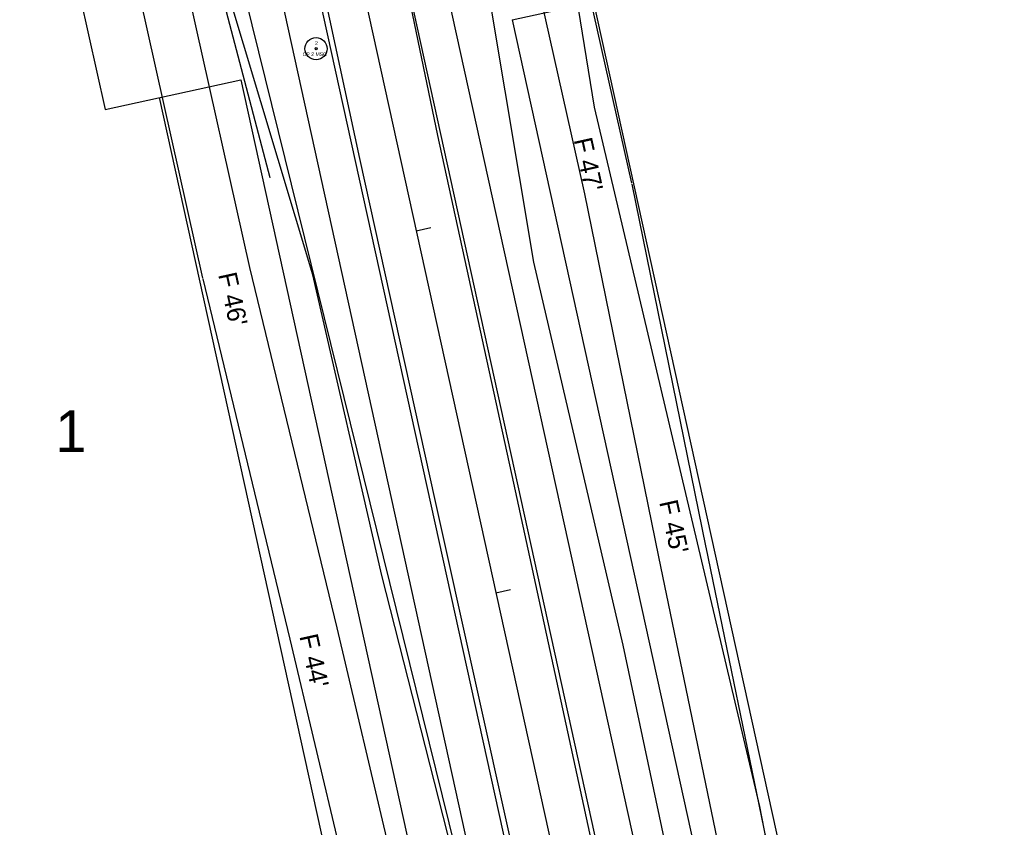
# Model space of a CAD drawing. Extents: x 2519952 to 2531965, y 848341 to 887632.
# Drawn here: x 2521510 to 2521778.9, y 868929.6 to 869147.3 of the extents above; entities that cross this region are included whole.
import ezdxf

# ---------------------------------------------------------------- set-up
doc = ezdxf.new("R2010")
doc.units = 0
for name, color, linetype in [('RD_EV_JW', 7, 'Continuous'), ('RD_EX_DV_Prop', 7, 'Continuous'), ('RD_EX_DV_TX_Prop', 7, 'Continuous'), ('RD_EX_H2O', 7, 'Continuous'), ('RD_EX_Road', 7, 'Continuous'), ('RD_EX_RW', 7, 'Continuous'), ('RD_EX_VEG', 7, 'Continuous'), ('RD_HC_Cl', 7, 'Continuous'), ('RD_HC_Data', 7, 'Continuous'), ('RD_HC_Data_Tic', 7, 'Continuous'), ('RD_HC_txCode', 7, 'Continuous'), ('RD_PD_CstnLmt', 7, 'Continuous'), ('RD_PD_DR_ErosCtrl', 7, 'Continuous'), ('RD_PD_Final_TrvlWay', 7, 'Continuous'), ('RD_PD_GR', 7, 'Continuous'), ('RD_PD_RW', 7, 'Continuous'), ('RD_PD_TX_CstnLmt', 7, 'Continuous'), ('RD_SMD_Locator', 7, 'Continuous')]:
    doc.layers.add(name, color=color, linetype=linetype)

msp = doc.modelspace()

# ---------------------------------------------------------------- linework, layer by layer
at = {"layer": 'RD_EV_JW'}
for points in [[(2521729.69, 868713.74), (2521695.24, 868873.24), (2521672.84, 868978.69), (2521648.76, 869082.03), (2521633.26, 869174.5), (2521621.89, 869258.79), (2521602.65, 869268.14)], [(2521612.58, 868633.3), (2521652.26, 868681.34), (2521670.78, 868698.5), (2521667.6, 868746.38), (2521632.57, 868900.09), (2521607.76, 868997.45), (2521589.09, 869078.55), (2521565.74, 869156.42), (2521555.56, 869195.14), (2521545.32, 869232.56)]]:
    msp.add_lwpolyline(points, dxfattribs=at)
at = {"layer": 'RD_EX_DV_Prop'}
for p, q in [((2521468.49, 869416.13), (2521533, 869123.15)), ((2521642.87, 869147.34), (2521750.4, 868659.04)), ((2521533, 869123.15), (2521569.63, 869131.21)), ((2521569.63, 869131.21), (2521677.15, 868642.91)), ((2521569.63, 869131.21), (2521677.15, 868642.91))]:
    msp.add_line(p, q, dxfattribs=at)
at = {"layer": 'RD_EX_H2O'}
msp.add_lwpolyline([(2521577.56, 869104.78), (2521548.5, 869215.22), (2521541.09, 869226.38), (2521555.3, 869258.21), (2521602.4, 869269.37), (2521612.65, 869269.66)], dxfattribs=at)
at = {"layer": 'RD_EX_Road'}
for p, q in [((2521622.8, 869116.12), (2521602.41, 869214.58)), ((2521601.82, 869109.96), (2521580.29, 869209.57)), ((2521643.39, 869022.37), (2521622.8, 869116.12)), ((2521622.17, 869017.45), (2521601.82, 869109.96)), ((2521664.33, 868925.84), (2521643.39, 869022.37)), ((2521643.93, 868919.83), (2521622.17, 869017.45))]:
    msp.add_line(p, q, dxfattribs=at)
at = {"layer": 'RD_EX_RW'}
for p, q in [((2521468.49, 869416.12), (2521533, 869123.14)), ((2521642.87, 869147.34), (2521679.5, 869155.4)), ((2521642.87, 869147.34), (2521750.4, 868659.04)), ((2521533, 869123.14), (2521569.63, 869131.21)), ((2521569.63, 869131.21), (2521677.15, 868642.91))]:
    msp.add_line(p, q, dxfattribs=at)
at = {"layer": 'RD_EX_VEG'}
for points in [[(2521585.06, 868581.88), (2521677.07, 868662.64), (2521629.4, 868916.48), (2521556.77, 869210.54), (2521553.88, 869240.28)], [(2521783.58, 868739.63), (2521750.99, 868722.72), (2521709.76, 868935.11), (2521665.16, 869123.82), (2521647.19, 869234.22)]]:
    msp.add_lwpolyline(points, dxfattribs=at)
at = {"layer": 'RD_HC_Cl'}
msp.add_line((2521425.99, 869957.86), (2521982.59, 867430.22), dxfattribs=at)
at = {"layer": 'RD_HC_Data'}
for radius in [3, 0.282]:
    msp.add_circle((2521589.97, 869139.58), radius, dxfattribs=at)
at = {"layer": 'RD_HC_Data_Tic'}
for p, q in [((2521617, 869090.44), (2521620.91, 869091.3)), ((2521638.51, 868992.78), (2521642.41, 868993.64))]:
    msp.add_line(p, q, dxfattribs=at)
at = {"layer": 'RD_PD_CstnLmt'}
for p, q in [((2521640.58, 869198.03), (2521662.43, 869100.45)), ((2521550.15, 869178.12), (2521572, 869080.53)), ((2521662.43, 869100.45), (2521682.43, 869002.45)), ((2521572, 869080.53), (2521595.53, 868983.32)), ((2521682.43, 869002.45), (2521702.69, 868904.52)), ((2521595.53, 868983.32), (2521618.61, 868886))]:
    msp.add_line(p, q, dxfattribs=at)
at = {"layer": 'RD_PD_DR_ErosCtrl'}
for p, q in [((2521653.26, 869200.87), (2521675.12, 869103.29)), ((2521537.47, 869175.28), (2521559.32, 869077.69)), ((2521675.17, 869103.05), (2521695.17, 869005.05)), ((2521559.37, 869077.47), (2521582.9, 868980.26)), ((2521695.16, 869005.09), (2521715.42, 868907.15)), ((2521582.88, 868980.32), (2521605.96, 868883))]:
    msp.add_line(p, q, dxfattribs=at)
at = {"layer": 'RD_PD_Final_TrvlWay'}
for p, q in [((2521526.57, 869556.91), (2521800.76, 868311.74)), ((2521503.13, 869551.75), (2521777.32, 868306.58))]:
    msp.add_line(p, q, dxfattribs=at)
at = {"layer": 'RD_PD_GR'}
for p, q in [((2521616.71, 869194.06), (2521775.31, 868473.81)), ((2521681.27, 868696.29), (2521573.74, 869184.59))]:
    msp.add_line(p, q, dxfattribs=at)
at = {"layer": 'RD_PD_RW'}
for p, q in [((2521664.85, 869152.17), (2521772.37, 868663.88)), ((2521547.65, 869126.37), (2521682.06, 868515.99))]:
    msp.add_line(p, q, dxfattribs=at)
at = {"layer": 'RD_SMD_Locator'}
for centre in [(2521589.97, 869139.58), (2521665.16, 869123.82), (2521622.8, 869116.12), (2521601.82, 869109.96), (2521577.56, 869104.78), (2521648.76, 869082.03), (2521589.09, 869078.55), (2521643.39, 869022.37), (2521622.17, 869017.45), (2521607.76, 868997.45), (2521672.84, 868978.69), (2521709.76, 868935.11)]:
    msp.add_circle(centre, 0.001, dxfattribs=at)

# ---------------------------------------------------------------- texts
at = {"layer": 'RD_EX_DV_TX_Prop'}
msp.add_text('1', height=11.32, dxfattribs=at).set_placement((2521519.6, 869030.74))
at = {"layer": 'RD_HC_txCode'}
for s, p in [('2', (2521589.68, 869140.58)), ('CP 2 MSC', (2521586.34, 869137.58))]:
    msp.add_text(s, height=1, dxfattribs=at).set_placement(p)
at = {"layer": 'RD_PD_CstnLmt'}
for s, p in [("F 46'", (2521563.52, 869078.66)), ("F 44'", (2521585.45, 868981.1))]:
    msp.add_text(s, height=5, rotation=282.4185, dxfattribs=at).set_placement(p)
at = {"layer": 'RD_PD_TX_CstnLmt'}
for s, p in [("F 47'", (2521659.48, 869115)), ("F 45'", (2521682.57, 869017.27))]:
    msp.add_text(s, height=5, rotation=282.4185, dxfattribs=at).set_placement(p)

doc.saveas('drawing.dxf')
